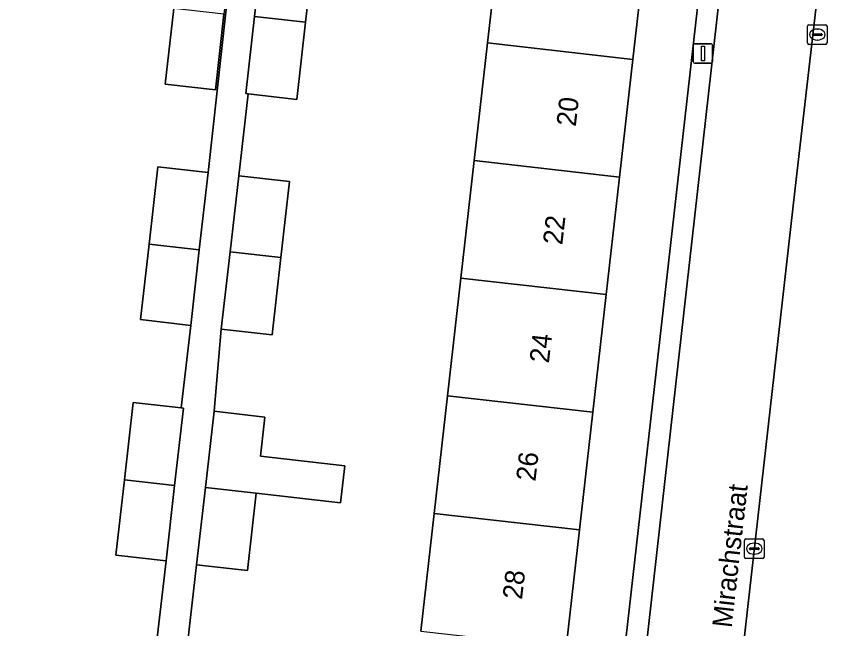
# Model space of a CAD drawing. Extents: x 161928 to 163071, y 386474 to 387428.
# Drawn here: x 162100.36 to 162142.19, y 386777.48 to 386808.82 of the extents above; entities that cross this region are included whole.
import ezdxf

# ---------------------------------------------------------------- set-up
doc = ezdxf.new("R2010")
doc.units = 0
for name, color, linetype in [('IMGEO_Erf', 7, 'Continuous'), ('IMGEO_Kolk', 7, 'Continuous'), ('IMGEO_Lichtmast', 7, 'Continuous'), ('IMGEO_Openbare_ruimte_label', 7, 'Continuous'), ('IMGEO_Pand', 7, 'Continuous'), ('IMGEO_Pand_nummerreeks', 7, 'Continuous'), ('IMGEO_Parkeervlak_open', 7, 'Continuous'), ('IMGEO_Rijbaan_lokaal_open', 7, 'Continuous'), ('IMGEO_Voetpad_open', 7, 'Continuous')]:
    doc.layers.add(name, color=color, linetype=linetype)

msp = doc.modelspace()

# ---------------------------------------------------------------- linework, layer by layer
at = {"layer": 'IMGEO_Erf'}
for points in [[(162094.742, 386767.943), (162106.503, 386766.612), (162106.762, 386768.886), (162104.189, 386769.179), (162104.629, 386773.043), (162105.08, 386777.003), (162107.543, 386776.723), (162108.024, 386780.945), (162105.451, 386781.238), (162105.891, 386785.102), (162106.342, 386789.062), (162108.805, 386788.782), (162109.286, 386793.003), (162106.713, 386793.296), (162107.153, 386797.16), (162107.604, 386801.12), (162110.177, 386800.827), (162111.754, 386815.094)], [(162121.057, 386777.355), (162121.742, 386783.377), (162122.426, 386789.399), (162123.11, 386795.42), (162123.795, 386801.441), (162124.479, 386807.461), (162124.613, 386808.642), (162125.178, 386813.61)], [(162115.607, 386812.423), (162115.163, 386808.519), (162114.713, 386804.57), (162112.219, 386804.854), (162111.741, 386800.661), (162114.346, 386800.364), (162113.903, 386796.469), (162113.452, 386792.511), (162110.847, 386792.808), (162110.479, 386788.602), (162113.084, 386788.305), (162112.857, 386786.306), (162117.166, 386785.817), (162116.951, 386783.92), (162112.641, 386784.41), (162112.19, 386780.452), (162109.585, 386780.749), (162107.966, 386766.515)]]:
    msp.add_lwpolyline(points, dxfattribs=at)
for points in [[(162107.974, 386805.355), (162108.414, 386809.219), (162108.865, 386813.179), (162111.438, 386812.886), (162110.987, 386808.927), (162110.547, 386805.062)], [(162135.581, 386812.449), (162132.619, 386812.763), (162131.92, 386806.616), (162131.236, 386800.595), (162130.552, 386794.574), (162129.868, 386788.553), (162129.183, 386782.531), (162128.499, 386776.51), (162127.815, 386770.489), (162127.116, 386764.34), (162130.092, 386764.003)]]:
    msp.add_lwpolyline(points, close=True, dxfattribs=at)
at = {"layer": 'IMGEO_Kolk'}
for p, q in [((162140.855, 386807.46), (162140.855, 386808.312)), ((162140.93, 386808.386), (162141.782, 386808.386)), ((162141.856, 386808.312), (162141.856, 386807.46)), ((162141.114, 386807.88), (162141.114, 386807.892)), ((162141.552, 386807.843), (162141.154, 386807.843)), ((162141.157, 386807.929), (162141.555, 386807.929)), ((162141.343, 386808.166), (162141.368, 386808.166)), ((162141.598, 386807.892), (162141.598, 386807.88)), ((162141.782, 386807.386), (162140.93, 386807.386)), ((162141.366, 386807.606), (162141.341, 386807.606)), ((162137.629, 386781.145), (162137.629, 386781.997)), ((162137.704, 386782.071), (162138.556, 386782.071)), ((162138.117, 386781.851), (162138.142, 386781.851)), ((162138.63, 386781.997), (162138.63, 386781.145)), ((162137.888, 386781.565), (162137.888, 386781.577)), ((162138.326, 386781.528), (162137.928, 386781.528)), ((162137.931, 386781.614), (162138.329, 386781.614)), ((162138.372, 386781.577), (162138.372, 386781.565)), ((162138.556, 386781.071), (162137.704, 386781.071)), ((162138.14, 386781.291), (162138.115, 386781.291))]:
    msp.add_line(p, q, dxfattribs=at)
for points in [[(162140.855, 386807.46), (162140.855, 386808.312)], [(162140.93, 386808.386), (162141.782, 386808.386)], [(162141.856, 386808.312), (162141.856, 386807.46)], [(162141.782, 386807.386), (162140.93, 386807.386)], [(162137.629, 386781.145), (162137.629, 386781.997)], [(162137.704, 386782.071), (162138.556, 386782.071)], [(162138.63, 386781.997), (162138.63, 386781.145)], [(162138.556, 386781.071), (162137.704, 386781.071)]]:
    msp.add_lwpolyline(points, dxfattribs=at)
for centre, radius, start, end in [((162140.932, 386808.31), 0.0765, 91.552, 178.448), ((162140.932, 386808.31), 0.0765, 91.552, 178.448), ((162141.78, 386808.31), 0.0765, 1.552, 88.448), ((162141.78, 386808.31), 0.0765, 1.552, 88.448), ((162141.154, 386807.889), 0.0403, 85.8775, 175.7526), ((162141.151, 386807.879), 0.0366, 178.938, 274.7102), ((162141.555, 386807.886), 0.043, 264.8664, 352.4533), ((162141.559, 386807.891), 0.0386, 1.7309, 96.639), ((162140.932, 386807.462), 0.0765, 181.552, 268.448), ((162140.932, 386807.462), 0.0765, 181.552, 268.448), ((162141.78, 386807.462), 0.0765, 271.552, 358.448), ((162141.78, 386807.462), 0.0765, 271.552, 358.448), ((162137.706, 386781.995), 0.0765, 91.552, 178.448), ((162137.706, 386781.995), 0.0765, 91.552, 178.448), ((162138.554, 386781.995), 0.0765, 1.552, 88.448), ((162138.554, 386781.995), 0.0765, 1.552, 88.448), ((162137.928, 386781.574), 0.0403, 85.8775, 175.7526), ((162137.925, 386781.564), 0.0366, 178.938, 274.7102), ((162138.329, 386781.571), 0.043, 264.8664, 352.4533), ((162138.333, 386781.576), 0.0386, 1.7309, 96.639), ((162137.706, 386781.147), 0.0765, 181.552, 268.448), ((162137.706, 386781.147), 0.0765, 181.552, 268.448), ((162138.554, 386781.147), 0.0765, 271.552, 358.448), ((162138.554, 386781.147), 0.0765, 271.552, 358.448)]:
    msp.add_arc(centre, radius, start, end, dxfattribs=at)
for centre, major_axis, ratio, start_param, end_param in [((162141.342, 386807.886), (-0.387, 0.002), 0.722429, 4.712389, 7.853982), ((162141.367, 386807.886), (-0.39, 0.002), 0.717154, 1.570796, 4.712389), ((162138.116, 386781.571), (-0.387, 0.002), 0.722429, 4.712389, 7.853982), ((162138.141, 386781.571), (-0.39, 0.002), 0.717154, 1.570796, 4.712389)]:
    msp.add_ellipse(centre, major_axis=major_axis, ratio=ratio, start_param=start_param, end_param=end_param, dxfattribs=at)
at = {"layer": 'IMGEO_Lichtmast'}
for p, q in [((162135.104, 386807.416), (162135.894, 386807.416)), ((162135.894, 386807.416), (162135.104, 386807.416)), ((162135.004, 386806.516), (162135.004, 386807.316)), ((162135.004, 386807.316), (162135.004, 386806.516)), ((162135.994, 386807.316), (162135.994, 386806.516)), ((162135.994, 386806.516), (162135.994, 386807.316)), ((162135.894, 386806.416), (162135.104, 386806.416)), ((162135.104, 386806.416), (162135.894, 386806.416))]:
    msp.add_line(p, q, dxfattribs=at)
msp.add_lwpolyline([(162135.424, 386807.291), (162135.574, 386807.291), (162135.574, 386806.541), (162135.424, 386806.541), (162135.424, 386807.291)], dxfattribs=at)
for centre, start, end in [((162135.104, 386807.316), 90, 180), ((162135.104, 386807.316), 90, 180), ((162135.894, 386807.316), 0, 90), ((162135.894, 386807.316), 360, 90), ((162135.104, 386806.516), 180, 270), ((162135.104, 386806.516), 180, 270), ((162135.894, 386806.516), 270, 0), ((162135.894, 386806.516), 270, 0)]:
    msp.add_arc(centre, 0.1, start, end, dxfattribs=at)
at = {"layer": 'IMGEO_Pand'}
for points in [[(162125.178, 386813.61), (162124.613, 386808.642), (162124.479, 386807.461), (162131.92, 386806.616), (162132.619, 386812.763)], [(162115.163, 386808.519), (162115.607, 386812.423), (162113.002, 386812.72), (162112.557, 386808.815)], [(162108.414, 386809.219), (162107.974, 386805.355), (162110.547, 386805.062), (162110.987, 386808.927)], [(162115.163, 386808.519), (162112.557, 386808.815), (162112.108, 386804.867), (162112.219, 386804.854), (162114.713, 386804.57)], [(162124.479, 386807.461), (162123.795, 386801.441), (162131.236, 386800.595), (162131.92, 386806.616)], [(162110.177, 386800.827), (162107.604, 386801.12), (162107.153, 386797.16), (162109.726, 386796.868)], [(162130.552, 386794.574), (162131.236, 386800.595), (162123.795, 386801.441), (162123.11, 386795.42)], [(162114.346, 386800.364), (162111.741, 386800.661), (162111.297, 386796.765), (162113.903, 386796.469)], [(162106.713, 386793.296), (162109.286, 386793.003), (162109.726, 386796.868), (162107.153, 386797.16)], [(162110.847, 386792.808), (162113.452, 386792.511), (162113.903, 386796.469), (162111.297, 386796.765)], [(162129.868, 386788.553), (162130.552, 386794.574), (162123.11, 386795.42), (162122.426, 386789.399)], [(162129.183, 386782.531), (162129.868, 386788.553), (162122.426, 386789.399), (162121.742, 386783.377)], [(162108.915, 386788.769), (162108.805, 386788.782), (162106.342, 386789.062), (162105.891, 386785.102), (162108.464, 386784.81)], [(162113.084, 386788.305), (162110.479, 386788.602), (162110.035, 386784.706), (162112.641, 386784.41), (162116.951, 386783.92), (162117.166, 386785.817), (162112.857, 386786.306)], [(162105.451, 386781.238), (162108.024, 386780.945), (162108.464, 386784.81), (162105.891, 386785.102)], [(162109.585, 386780.749), (162112.19, 386780.452), (162112.641, 386784.41), (162110.035, 386784.706)], [(162121.742, 386783.377), (162121.057, 386777.355), (162128.499, 386776.51), (162129.183, 386782.531)]]:
    msp.add_lwpolyline(points, close=True, dxfattribs=at)
at = {"layer": 'IMGEO_Parkeervlak_open'}
msp.add_lwpolyline([(162145.548, 386811.148), (162141.554, 386811.582), (162140.199, 386799.863), (162135.66, 386759.762)], dxfattribs=at)
at = {"layer": 'IMGEO_Rijbaan_lokaal_open'}
for points in [[(162140.199, 386799.863), (162141.554, 386811.582), (162138.598, 386811.904)], [(162136.354, 386809.876), (162129.914, 386752.746), (162134.807, 386752.229), (162135.66, 386759.762), (162140.199, 386799.863)]]:
    msp.add_lwpolyline(points, dxfattribs=at)
at = {"layer": 'IMGEO_Voetpad_open'}
for points in [[(162111.754, 386815.094), (162110.177, 386800.827), (162109.726, 386796.868), (162109.286, 386793.003), (162108.805, 386788.782), (162108.915, 386788.769), (162108.464, 386784.81), (162108.024, 386780.945), (162107.543, 386776.723), (162107.653, 386776.71), (162107.202, 386772.751), (162106.762, 386768.886), (162106.503, 386766.612), (162094.742, 386767.943)], [(162107.966, 386766.515), (162109.585, 386780.749), (162110.035, 386784.706), (162110.479, 386788.602), (162110.847, 386792.808), (162111.297, 386796.765), (162111.741, 386800.661), (162112.219, 386804.854), (162112.108, 386804.867), (162112.557, 386808.815), (162113.002, 386812.72)], [(162138.598, 386811.904), (162135.581, 386812.449), (162130.092, 386764.003), (162129.93, 386762.572), (162129.066, 386754.9), (162128.987, 386754.54)], [(162127.26, 386753.058), (162129.914, 386752.746), (162136.354, 386809.876)]]:
    msp.add_lwpolyline(points, dxfattribs=at)

# ---------------------------------------------------------------- texts
at = {"layer": 'IMGEO_Openbare_ruimte_label'}
msp.add_text('Mirachstraat', height=1, rotation=83.5143, dxfattribs=at).set_placement((162136.967, 386777.492))
at = {"layer": 'IMGEO_Pand_nummerreeks'}
for s, p in [('20', (162128.991, 386803.15)), ('22', (162128.302, 386797.091)), ('24', (162127.615, 386791.041)), ('26', (162126.927, 386784.989)), ('28', (162126.239, 386778.939))]:
    msp.add_text(s, height=1, rotation=83.5165, dxfattribs=at).set_placement(p)

doc.saveas('drawing.dxf')
